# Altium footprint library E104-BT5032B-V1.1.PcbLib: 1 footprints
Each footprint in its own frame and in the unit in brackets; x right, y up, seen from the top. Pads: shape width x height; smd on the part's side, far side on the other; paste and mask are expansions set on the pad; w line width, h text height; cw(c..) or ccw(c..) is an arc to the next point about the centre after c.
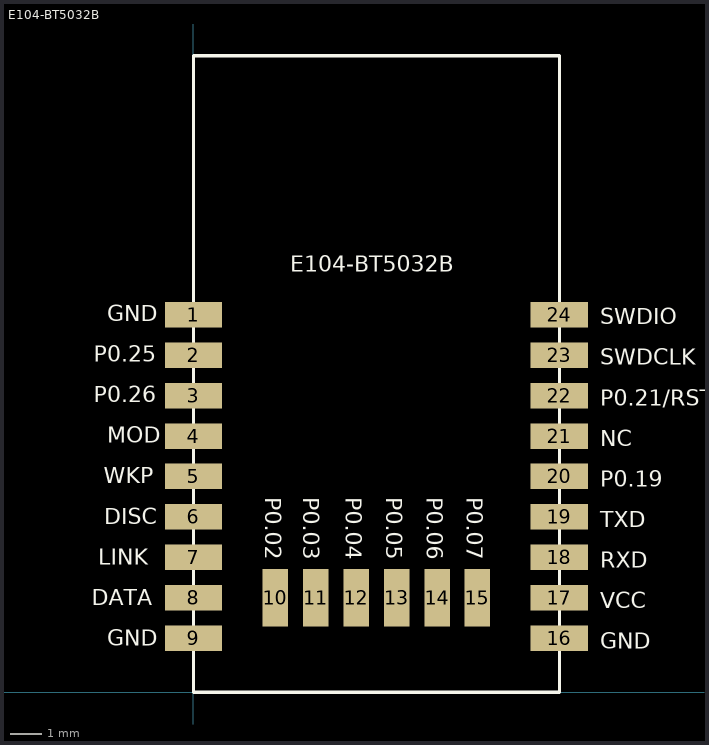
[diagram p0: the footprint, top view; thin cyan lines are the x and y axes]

## E104-BT5032B [mm]
pads (24):
  rect 1.8x0.8 smd: 1(0,11.86) 2(0,10.59) 3(0,9.32) 4(0,8.05) 5(0,6.78) 6(0,5.51) 7(0,4.24) 8(0,2.97) 9(0,1.7) 16(11.5,1.7) 17(11.5,2.97) 18(11.5,4.24) 19(11.5,5.51) 20(11.5,6.78) 21(11.5,8.05) 22(11.5,9.32) 23(11.5,10.59) 24(11.5,11.86)
  rect 0.8x1.8 smd: 10(2.575,2.97) 11(3.845,2.97) 12(5.115,2.97) 13(6.385,2.97) 14(7.655,2.97) 15(8.925,2.97)
Top Overlay:
  lines w0.1: 0,0 11.5,0 11.5,20 0,20 0,0
  text "E104-BT5032B" at 3.048,13.208 h0.5
  text "GND" at -2.709,11.66 h0.5
  text "P0.25" at -3.137,10.385 h0.5
  text "P0.26" at -3.137,9.11 h0.5
  text "MOD" at -2.709,7.835 h0.5
  text "WKP" at -2.812,6.56 h0.5
  text "DISC" at -2.806,5.285 h0.5
  text "LINK" at -2.997,4.01 h0.5
  text "DATA" at -3.2,2.735 h0.5
  text "VCC" at 12.791,2.635 h0.5
  text "RXD" at 12.791,3.91 h0.5
  text "TXD" at 12.791,5.185 h0.5
  text "P0.19" at 12.791,6.46 h0.5
  text "NC" at 12.791,7.735 h0.5
  text "P0.21/RST" at 12.791,9.01 h0.5
  text "SWDCLK" at 12.791,10.285 h0.5
  text "SWDIO" at 12.791,11.56 h0.5
  text "P0.07" at 8.595,6.123 h0.5
  text "P0.05" at 6.055,6.123 h0.5
  text "P0.04" at 4.785,6.123 h0.5
  text "P0.02" at 2.256,6.123 h0.5
  text "P0.06" at 7.325,6.123 h0.5
  text "P0.03" at 3.454,6.123 h0.5
  text "GND" at -2.709,1.46 h0.5
  text "GND" at 12.791,1.36 h0.5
